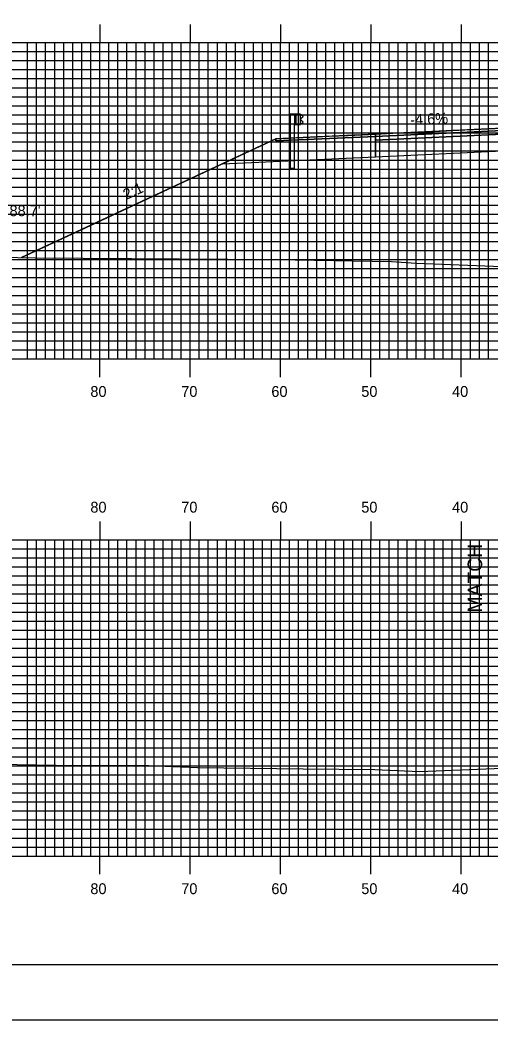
# Model space of a CAD drawing. Extents: x 1756675 to 1757019, y 442591 to 442811.
# Drawn here: x 1756752.2 to 1756804.3, y 442590.5 to 442701.2 of the extents above; entities that cross this region are included whole.
import ezdxf

# ---------------------------------------------------------------- set-up
doc = ezdxf.new("R2010")
doc.units = 0
for name, color, linetype in [('ANNOTATION', 7, 'Continuous'), ('BORDER', 7, 'Continuous'), ('D_Guardrail_Beam_Lt', 7, 'Continuous'), ('D_Roadway_Centerline', 7, 'Continuous'), ('D_Roadway_Edge_Shoulder', 7, 'Continuous'), ('D_Roadway_Edge_TW', 7, 'Continuous'), ('D_Roadway_Pavement', 7, 'Continuous'), ('D_Roadway_SlopeLines', 7, 'Continuous'), ('D_Roadway_SubGrade', 7, 'Continuous'), ('D_Text_Standard', 7, 'Continuous'), ('H_V ANNOTATION', 7, 'Continuous'), ('MAJOR', 7, 'Continuous'), ('MINOR', 7, 'Continuous'), ('PLOT BOUNDARY', 7, 'Continuous'), ('S_Roadway_Centerline', 7, 'Continuous')]:
    doc.layers.add(name, color=color, linetype=linetype)

msp = doc.modelspace()

# ---------------------------------------------------------------- linework, layer by layer
at = {"layer": 'BORDER'}
msp.add_lwpolyline([(1756691.48, 442596.67), (1757011.48, 442596.67), (1757011.48, 442806.67), (1756691.48, 442806.67)], close=True, dxfattribs=at)
at = {"layer": 'D_Guardrail_Beam_Lt'}
for p, q in [((1756782.14, 442690.75), (1756782.14, 442684.75)), ((1756782.61, 442690.75), (1756782.14, 442690.75)), ((1756783.3, 442690.75), (1756782.61, 442690.75)), ((1756782.61, 442690.75), (1756782.61, 442689.59)), ((1756782.67, 442690.75), (1756782.67, 442689.59)), ((1756782.78, 442690.75), (1756782.78, 442689.59)), ((1756783.3, 442689.59), (1756783.3, 442690.75)), ((1756783.3, 442690.67), (1756783.37, 442690.66)), ((1756783.39, 442690.65), (1756783.53, 442690.55)), ((1756782.61, 442689.59), (1756783.3, 442689.59)), ((1756782.63, 442684.75), (1756782.63, 442689.59)), ((1756783.3, 442690.21), (1756783.3, 442690.14)), ((1756783.37, 442689.69), (1756783.3, 442689.67)), ((1756783.53, 442690.41), (1756783.34, 442690.27)), ((1756783.34, 442690.07), (1756783.53, 442689.93)), ((1756783.53, 442689.79), (1756783.39, 442689.69)), ((1756782.63, 442684.75), (1756782.14, 442684.75))]:
    msp.add_line(p, q, dxfattribs=at)
for centre, major_axis, start_param, end_param in [((1756783.36, 442690.62), (0.0417, 0), 0.959931, 1.376053), ((1756783.48, 442690.48), (0.0877, 0), 5.323254, 7.243116), ((1756783.38, 442690.21), (-0.0789, 0), 5.323254, 6.283185), ((1756783.38, 442690.14), (-0.0789, 0), 6.283185, 7.243116), ((1756783.36, 442689.73), (0.0417, 0), 4.907132, 5.323254), ((1756783.48, 442689.86), (0.0877, 0), 5.323254, 7.243116)]:
    msp.add_ellipse(centre, major_axis=major_axis, ratio=0.995501, start_param=start_param, end_param=end_param, dxfattribs=at)
at = {"layer": 'D_Roadway_Centerline'}
msp.add_lwpolyline([(1756752.4, 442674.88), (1756759.58, 442678.22), (1756760.76, 442678.76), (1756780.56, 442688.03), (1756782.62, 442688.13), (1756783.25, 442688.16), (1756783.57, 442688.17), (1756786.44, 442688.3), (1756788.56, 442688.4), (1756791.6, 442688.54), (1756794.13, 442688.66), (1756798.09, 442688.84), (1756801.47, 442689), (1756802.43, 442689.04), (1756805.65, 442689.19), (1756809.65, 442689.16), (1756815.68, 442689.12)], dxfattribs=at)
at = {"layer": 'D_Roadway_Edge_Shoulder'}
msp.add_lwpolyline([(1756791.6, 442688.54), (1756783.57, 442688.17), (1756783.57, 442688.17), (1756780.56, 442688.03), (1756780.56, 442687.78), (1756791.6, 442688.29)], close=True, dxfattribs=at)
at = {"layer": 'D_Roadway_Edge_TW'}
msp.add_lwpolyline([(1756805.65, 442689.19), (1756791.6, 442688.54), (1756791.6, 442688.29), (1756805.65, 442688.94)], close=True, dxfattribs=at)
at = {"layer": 'D_Roadway_Pavement'}
msp.add_lwpolyline([(1756805.65, 442688.94), (1756791.6, 442688.29), (1756791.6, 442687.88), (1756805.65, 442688.52)], close=True, dxfattribs=at)
msp.add_lwpolyline([(1756791.6, 442688.29), (1756791.6, 442687.88)], dxfattribs=at)
msp.add_lwpolyline([(1756791.6, 442688.29), (1756791.6, 442687.88)], dxfattribs=at)
at = {"layer": 'D_Roadway_SlopeLines'}
msp.add_lwpolyline([(1756780.56, 442688.03), (1756752.4, 442674.88)], dxfattribs=at)
at = {"layer": 'D_Roadway_SubGrade'}
for points in [[(1756791.6, 442687.88), (1756791.6, 442688.29), (1756780.56, 442687.78), (1756780.56, 442688.03), (1756774.61, 442685.25), (1756791.6, 442686.04)], [(1756805.65, 442688.52), (1756791.6, 442687.88), (1756791.6, 442686.04), (1756805.65, 442686.69)]]:
    msp.add_lwpolyline(points, close=True, dxfattribs=at)
at = {"layer": 'MAJOR'}
for p, q in [((1756761.08, 442700.67), (1756761.08, 442698.67)), ((1756771.08, 442700.67), (1756771.08, 442698.67)), ((1756781.08, 442700.67), (1756781.08, 442698.67)), ((1756791.08, 442700.67), (1756791.08, 442698.67)), ((1756801.08, 442700.67), (1756801.08, 442698.67)), ((1756701.08, 442698.67), (1756981.08, 442698.67)), ((1756701.08, 442698.67), (1756981.08, 442698.67)), ((1756761.08, 442663.67), (1756761.08, 442698.67)), ((1756771.08, 442663.67), (1756771.08, 442698.67)), ((1756781.08, 442663.67), (1756781.08, 442698.67)), ((1756791.08, 442663.67), (1756791.08, 442698.67)), ((1756801.08, 442663.67), (1756801.08, 442698.67)), ((1756701.08, 442693.67), (1756981.08, 442693.67)), ((1756701.08, 442688.67), (1756981.08, 442688.67)), ((1756701.08, 442683.67), (1756981.08, 442683.67)), ((1756701.08, 442678.67), (1756981.08, 442678.67)), ((1756701.08, 442673.67), (1756981.08, 442673.67)), ((1756701.08, 442668.67), (1756981.08, 442668.67)), ((1756701.08, 442663.67), (1756981.08, 442663.67)), ((1756701.08, 442663.67), (1756981.08, 442663.67)), ((1756761.08, 442661.66), (1756761.08, 442663.67)), ((1756771.08, 442661.66), (1756771.08, 442663.67)), ((1756781.08, 442661.66), (1756781.08, 442663.67)), ((1756791.08, 442661.66), (1756791.08, 442663.67)), ((1756801.08, 442661.66), (1756801.08, 442663.67)), ((1756761.08, 442645.67), (1756761.08, 442643.67)), ((1756771.08, 442645.67), (1756771.08, 442643.67)), ((1756781.08, 442645.67), (1756781.08, 442643.67)), ((1756791.08, 442645.67), (1756791.08, 442643.67)), ((1756801.08, 442645.67), (1756801.08, 442643.67)), ((1756701.08, 442643.67), (1756981.08, 442643.67)), ((1756701.08, 442643.67), (1756981.08, 442643.67)), ((1756761.08, 442608.67), (1756761.08, 442643.67)), ((1756771.08, 442608.67), (1756771.08, 442643.67)), ((1756781.08, 442608.67), (1756781.08, 442643.67)), ((1756791.08, 442608.67), (1756791.08, 442643.67)), ((1756801.08, 442608.67), (1756801.08, 442643.67)), ((1756701.08, 442638.67), (1756981.08, 442638.67)), ((1756701.08, 442633.67), (1756981.08, 442633.67)), ((1756701.08, 442628.67), (1756981.08, 442628.67)), ((1756701.08, 442623.67), (1756981.08, 442623.67)), ((1756701.08, 442618.67), (1756981.08, 442618.67)), ((1756701.08, 442613.67), (1756981.08, 442613.67)), ((1756701.08, 442608.67), (1756981.08, 442608.67)), ((1756701.08, 442608.67), (1756981.08, 442608.67)), ((1756761.08, 442606.66), (1756761.08, 442608.67)), ((1756771.08, 442606.66), (1756771.08, 442608.67)), ((1756781.08, 442606.66), (1756781.08, 442608.67)), ((1756791.08, 442606.66), (1756791.08, 442608.67)), ((1756801.08, 442606.66), (1756801.08, 442608.67))]:
    msp.add_line(p, q, dxfattribs=at)
at = {"layer": 'MINOR'}
for p, q in [((1756753.08, 442663.67), (1756753.08, 442698.67)), ((1756754.08, 442663.67), (1756754.08, 442698.67)), ((1756755.08, 442663.67), (1756755.08, 442698.67)), ((1756756.08, 442663.67), (1756756.08, 442698.67)), ((1756757.08, 442663.67), (1756757.08, 442698.67)), ((1756758.08, 442663.67), (1756758.08, 442698.67)), ((1756759.08, 442663.67), (1756759.08, 442698.67)), ((1756760.08, 442663.67), (1756760.08, 442698.67)), ((1756762.08, 442663.67), (1756762.08, 442698.67)), ((1756763.08, 442663.67), (1756763.08, 442698.67)), ((1756764.08, 442663.67), (1756764.08, 442698.67)), ((1756765.08, 442663.67), (1756765.08, 442698.67)), ((1756766.08, 442663.67), (1756766.08, 442698.67)), ((1756767.08, 442663.67), (1756767.08, 442698.67)), ((1756768.08, 442663.67), (1756768.08, 442698.67)), ((1756769.08, 442663.67), (1756769.08, 442698.67)), ((1756770.08, 442663.67), (1756770.08, 442698.67)), ((1756772.08, 442663.67), (1756772.08, 442698.67)), ((1756773.08, 442663.67), (1756773.08, 442698.67)), ((1756774.08, 442663.67), (1756774.08, 442698.67)), ((1756775.08, 442663.67), (1756775.08, 442698.67)), ((1756776.08, 442663.67), (1756776.08, 442698.67)), ((1756777.08, 442663.67), (1756777.08, 442698.67)), ((1756778.08, 442663.67), (1756778.08, 442698.67)), ((1756779.08, 442663.67), (1756779.08, 442698.67)), ((1756780.08, 442663.67), (1756780.08, 442698.67)), ((1756782.08, 442663.67), (1756782.08, 442698.67)), ((1756783.08, 442663.67), (1756783.08, 442698.67)), ((1756784.08, 442663.67), (1756784.08, 442698.67)), ((1756785.08, 442663.67), (1756785.08, 442698.67)), ((1756786.08, 442663.67), (1756786.08, 442698.67)), ((1756787.08, 442663.67), (1756787.08, 442698.67)), ((1756788.08, 442663.67), (1756788.08, 442698.67)), ((1756789.08, 442663.67), (1756789.08, 442698.67)), ((1756790.08, 442663.67), (1756790.08, 442698.67)), ((1756792.08, 442663.67), (1756792.08, 442698.67)), ((1756793.08, 442663.67), (1756793.08, 442698.67)), ((1756794.08, 442663.67), (1756794.08, 442698.67)), ((1756795.08, 442663.67), (1756795.08, 442698.67)), ((1756796.08, 442663.67), (1756796.08, 442698.67)), ((1756797.08, 442663.67), (1756797.08, 442698.67)), ((1756798.08, 442663.67), (1756798.08, 442698.67)), ((1756799.08, 442663.67), (1756799.08, 442698.67)), ((1756800.08, 442663.67), (1756800.08, 442698.67)), ((1756802.08, 442663.67), (1756802.08, 442698.67)), ((1756803.08, 442663.67), (1756803.08, 442698.67)), ((1756804.08, 442663.67), (1756804.08, 442698.67)), ((1756701.08, 442697.67), (1756981.08, 442697.67)), ((1756701.08, 442696.67), (1756981.08, 442696.67)), ((1756701.08, 442695.67), (1756981.08, 442695.67)), ((1756701.08, 442694.67), (1756981.08, 442694.67)), ((1756701.08, 442692.67), (1756981.08, 442692.67)), ((1756701.08, 442691.67), (1756981.08, 442691.67)), ((1756701.08, 442690.67), (1756981.08, 442690.67)), ((1756701.08, 442689.67), (1756981.08, 442689.67)), ((1756701.08, 442687.67), (1756981.08, 442687.67)), ((1756701.08, 442686.67), (1756981.08, 442686.67)), ((1756701.08, 442685.67), (1756981.08, 442685.67)), ((1756701.08, 442684.67), (1756981.08, 442684.67)), ((1756701.08, 442682.67), (1756981.08, 442682.67)), ((1756701.08, 442681.67), (1756981.08, 442681.67)), ((1756701.08, 442680.67), (1756981.08, 442680.67)), ((1756701.08, 442679.67), (1756981.08, 442679.67)), ((1756701.08, 442677.67), (1756981.08, 442677.67)), ((1756701.08, 442676.67), (1756981.08, 442676.67)), ((1756701.08, 442675.67), (1756981.08, 442675.67)), ((1756701.08, 442674.67), (1756981.08, 442674.67)), ((1756701.08, 442672.67), (1756981.08, 442672.67)), ((1756701.08, 442671.67), (1756981.08, 442671.67)), ((1756701.08, 442670.67), (1756981.08, 442670.67)), ((1756701.08, 442669.67), (1756981.08, 442669.67)), ((1756701.08, 442667.67), (1756981.08, 442667.67)), ((1756701.08, 442666.67), (1756981.08, 442666.67)), ((1756701.08, 442665.67), (1756981.08, 442665.67)), ((1756701.08, 442664.67), (1756981.08, 442664.67)), ((1756753.08, 442608.67), (1756753.08, 442643.67)), ((1756754.08, 442608.67), (1756754.08, 442643.67)), ((1756755.08, 442608.67), (1756755.08, 442643.67)), ((1756756.08, 442608.67), (1756756.08, 442643.67)), ((1756757.08, 442608.67), (1756757.08, 442643.67)), ((1756758.08, 442608.67), (1756758.08, 442643.67)), ((1756759.08, 442608.67), (1756759.08, 442643.67)), ((1756760.08, 442608.67), (1756760.08, 442643.67)), ((1756762.08, 442608.67), (1756762.08, 442643.67)), ((1756763.08, 442608.67), (1756763.08, 442643.67)), ((1756764.08, 442608.67), (1756764.08, 442643.67)), ((1756765.08, 442608.67), (1756765.08, 442643.67)), ((1756766.08, 442608.67), (1756766.08, 442643.67)), ((1756767.08, 442608.67), (1756767.08, 442643.67)), ((1756768.08, 442608.67), (1756768.08, 442643.67)), ((1756769.08, 442608.67), (1756769.08, 442643.67)), ((1756770.08, 442608.67), (1756770.08, 442643.67)), ((1756772.08, 442608.67), (1756772.08, 442643.67)), ((1756773.08, 442608.67), (1756773.08, 442643.67)), ((1756774.08, 442608.67), (1756774.08, 442643.67)), ((1756775.08, 442608.67), (1756775.08, 442643.67)), ((1756776.08, 442608.67), (1756776.08, 442643.67)), ((1756777.08, 442608.67), (1756777.08, 442643.67)), ((1756778.08, 442608.67), (1756778.08, 442643.67)), ((1756779.08, 442608.67), (1756779.08, 442643.67)), ((1756780.08, 442608.67), (1756780.08, 442643.67)), ((1756782.08, 442608.67), (1756782.08, 442643.67)), ((1756783.08, 442608.67), (1756783.08, 442643.67)), ((1756784.08, 442608.67), (1756784.08, 442643.67)), ((1756785.08, 442608.67), (1756785.08, 442643.67)), ((1756786.08, 442608.67), (1756786.08, 442643.67)), ((1756787.08, 442608.67), (1756787.08, 442643.67)), ((1756788.08, 442608.67), (1756788.08, 442643.67)), ((1756789.08, 442608.67), (1756789.08, 442643.67)), ((1756790.08, 442608.67), (1756790.08, 442643.67)), ((1756792.08, 442608.67), (1756792.08, 442643.67)), ((1756793.08, 442608.67), (1756793.08, 442643.67)), ((1756794.08, 442608.67), (1756794.08, 442643.67)), ((1756795.08, 442608.67), (1756795.08, 442643.67)), ((1756796.08, 442608.67), (1756796.08, 442643.67)), ((1756797.08, 442608.67), (1756797.08, 442643.67)), ((1756798.08, 442608.67), (1756798.08, 442643.67)), ((1756799.08, 442608.67), (1756799.08, 442643.67)), ((1756800.08, 442608.67), (1756800.08, 442643.67)), ((1756802.08, 442608.67), (1756802.08, 442643.67)), ((1756803.08, 442608.67), (1756803.08, 442643.67)), ((1756804.08, 442608.67), (1756804.08, 442643.67)), ((1756701.08, 442642.67), (1756981.08, 442642.67)), ((1756701.08, 442641.67), (1756981.08, 442641.67)), ((1756701.08, 442640.67), (1756981.08, 442640.67)), ((1756701.08, 442639.67), (1756981.08, 442639.67)), ((1756701.08, 442637.67), (1756981.08, 442637.67)), ((1756701.08, 442636.67), (1756981.08, 442636.67)), ((1756701.08, 442635.67), (1756981.08, 442635.67)), ((1756701.08, 442634.67), (1756981.08, 442634.67)), ((1756701.08, 442632.67), (1756981.08, 442632.67)), ((1756701.08, 442631.67), (1756981.08, 442631.67)), ((1756701.08, 442630.67), (1756981.08, 442630.67)), ((1756701.08, 442629.67), (1756981.08, 442629.67)), ((1756701.08, 442627.67), (1756981.08, 442627.67)), ((1756701.08, 442626.67), (1756981.08, 442626.67)), ((1756701.08, 442625.67), (1756981.08, 442625.67)), ((1756701.08, 442624.67), (1756981.08, 442624.67)), ((1756701.08, 442622.67), (1756981.08, 442622.67)), ((1756701.08, 442621.67), (1756981.08, 442621.67)), ((1756701.08, 442620.67), (1756981.08, 442620.67)), ((1756701.08, 442619.67), (1756981.08, 442619.67)), ((1756701.08, 442617.67), (1756981.08, 442617.67)), ((1756701.08, 442616.67), (1756981.08, 442616.67)), ((1756701.08, 442615.67), (1756981.08, 442615.67)), ((1756701.08, 442614.67), (1756981.08, 442614.67)), ((1756701.08, 442612.67), (1756981.08, 442612.67)), ((1756701.08, 442611.67), (1756981.08, 442611.67)), ((1756701.08, 442610.67), (1756981.08, 442610.67)), ((1756701.08, 442609.67), (1756981.08, 442609.67))]:
    msp.add_line(p, q, dxfattribs=at)
at = {"layer": 'PLOT BOUNDARY'}
msp.add_lwpolyline([(1756675.3, 442590.55), (1757015.3, 442590.55), (1757015.3, 442810.55), (1756675.3, 442810.55)], close=True, dxfattribs=at)
at = {"layer": 'S_Roadway_Centerline'}
for points in [[(1756701.08, 442674.81), (1756701.68, 442674.81), (1756706.12, 442674.79), (1756709.1, 442674.81), (1756750.01, 442674.91), (1756753.92, 442674.86), (1756780.55, 442674.65), (1756793.34, 442674.46), (1756796.09, 442674.27), (1756805.61, 442673.9), (1756808.09, 442673.88), (1756821.91, 442673.54), (1756842.06, 442673.4), (1756851.64, 442673.44), (1756857.38, 442673.52), (1756881.46, 442674.48), (1756884.01, 442674.46), (1756914.99, 442674.3), (1756935.3, 442674.49), (1756942.87, 442674.67), (1756956.22, 442674.7), (1756981.08, 442675.14)], [(1756747.56, 442618.88), (1756758.43, 442618.71), (1756759.88, 442618.72), (1756766.5, 442618.68), (1756771.87, 442618.48), (1756783.58, 442618.32), (1756791.51, 442618.24), (1756796.47, 442618.02), (1756810.22, 442618.58), (1756815.39, 442618.76), (1756815.66, 442618.74), (1756819.29, 442617.09), (1756823.12, 442615.79), (1756826, 442615.08), (1756836.89, 442615.06), (1756842.09, 442615.1), (1756848.85, 442615.19), (1756858.61, 442615.19), (1756868.93, 442615.18), (1756877.06, 442615.13), (1756889.06, 442615.07), (1756897.49, 442615.15), (1756901.77, 442615.11), (1756905.48, 442615.16)]]:
    msp.add_lwpolyline(points, dxfattribs=at)

# ---------------------------------------------------------------- texts
at = {"layer": 'ANNOTATION'}
for s, height, rotation, p in [('-4.6%', 1.2, 2.624, (1756795.45, 442689.52)), ('2:1', 1.2, 24.5072, (1756763.98, 442681.24)), ('MATCH', 1.6, 90, (1756803.38, 442635.61))]:
    msp.add_text(s, height=height, rotation=rotation, dxfattribs=at).set_placement(p)
at = {"layer": 'D_Text_Standard'}
msp.add_text("88.7'", height=1.2, dxfattribs=at).set_placement((1756751.08, 442679.46))
at = {"layer": 'H_V ANNOTATION'}
for s, p in [('80', (1756760.03, 442659.47)), ('70', (1756770.09, 442659.47)), ('60', (1756780.06, 442659.47)), ('50', (1756790.01, 442659.47)), ('40', (1756800.06, 442659.47)), ('80', (1756760.03, 442646.67)), ('70', (1756770.09, 442646.67)), ('60', (1756780.06, 442646.67)), ('50', (1756790.01, 442646.67)), ('40', (1756800.06, 442646.67)), ('80', (1756760.03, 442604.47)), ('70', (1756770.09, 442604.47)), ('60', (1756780.06, 442604.47)), ('50', (1756790.01, 442604.47)), ('40', (1756800.06, 442604.47))]:
    msp.add_text(s, height=1.2, dxfattribs=at).set_placement(p)

doc.saveas('drawing.dxf')
